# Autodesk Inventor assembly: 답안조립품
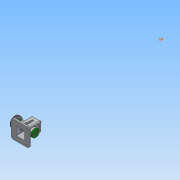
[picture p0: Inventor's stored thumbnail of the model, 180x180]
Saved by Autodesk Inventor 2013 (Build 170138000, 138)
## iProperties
Created: 2016-02
Part Number: 답안조립품
Document SubType Name: Assembly
Designer: Administrator
Author: Administrator
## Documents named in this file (16)
- C:\Users\Administrator\Desktop\460212V1018\답안조립품.iam
- C:\Users\Administrator\Desktop\460212V1018\본체.ipt
- C:\Users\Administrator\Desktop\460212V1018\V벨트풀리.ipt
- C:\Users\Administrator\Desktop\460212V1018\고정핀 1.2 x 10.ipt
- C:\Users\Administrator\Desktop\460212V1018\뒤커버.ipt
- C:\Users\Administrator\Desktop\460212V1018\링크.ipt
- C:\Users\Administrator\Desktop\460212V1018\멈춤나사 M3x8.ipt
- C:\Users\Administrator\Desktop\460212V1018\베어링 12 x 32 x 10.ipt
- C:\Users\Administrator\Desktop\460212V1018\볼트 M4 x 12.ipt
- C:\Users\Administrator\Desktop\460212V1018\부시.ipt
- C:\Users\Administrator\Desktop\460212V1018\슬라이드.ipt
- C:\Users\Administrator\Desktop\460212V1018\앞커버.ipt
- C:\Users\Administrator\Desktop\460212V1018\오일실 12 25 7.ipt
- C:\Users\Administrator\Desktop\460212V1018\키 4 x 4 x 10.ipt
- C:\Users\Administrator\Desktop\460212V1018\편심축.ipt
- C:\Users\Administrator\Desktop\460212V1018\핀 5 x 18.ipt
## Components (11 placed, 4 different names)
1. V벨트풀리:1 — 플러쉬:1
2. 고정핀 1.2 x 10:1 — 플러쉬:3
3. 핀 5 x 18:1 — 플러쉬:3
4. ISO 4762 M4 x 12:1
5. ISO 4762 M4 x 12:2
6. ISO 4762 M4 x 12:3
7. ISO 4762 M4 x 12:4
8. ISO 4762 M4 x 12:5
9. ISO 4762 M4 x 12:6
10. ISO 4762 M4 x 12:7
11. ISO 4762 M4 x 12:8
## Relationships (2: Flush 2)
- 플러쉬:1 [Flush]: V벨트풀리:1
- 플러쉬:3 [Flush]: 고정핀 1.2 x 10:1 ↔ 핀 5 x 18:1
